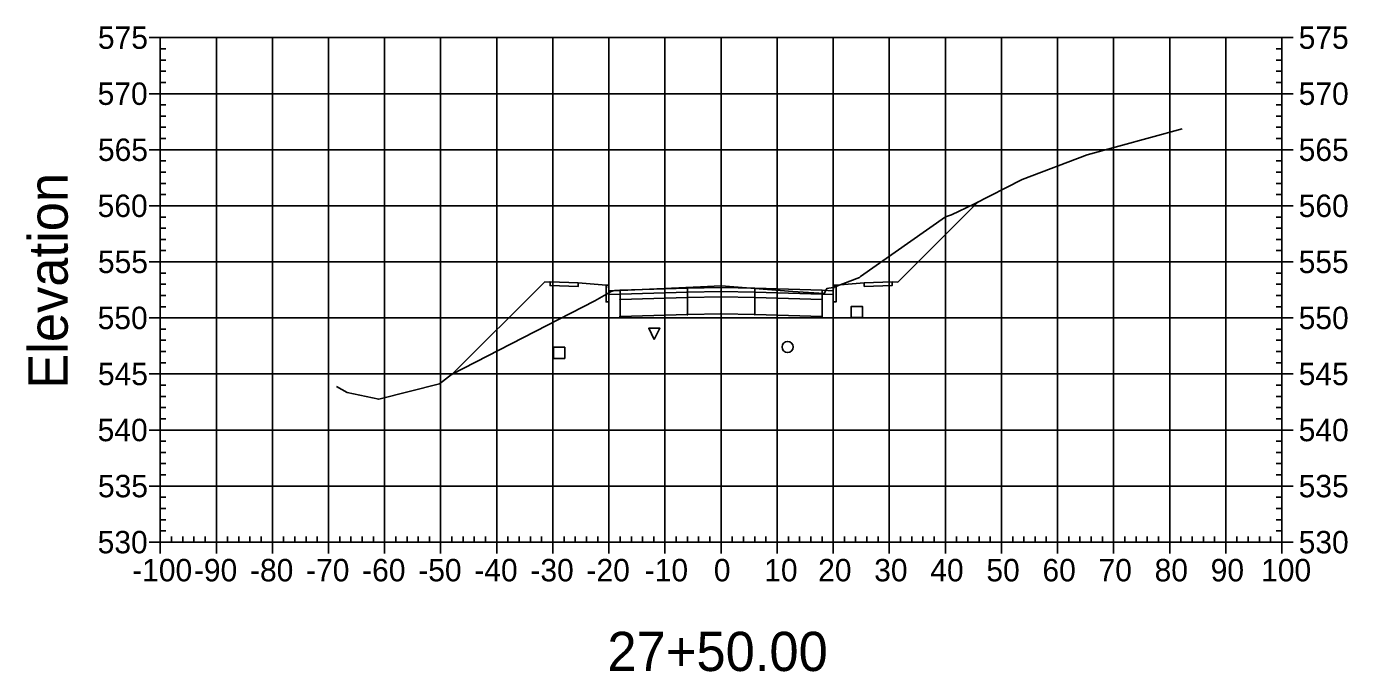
# Model space of a CAD drawing. Extents: x 704834 to 709892, y 372981 to 377533.
# Drawn here: x 708281 to 708516.6, y 376297.7 to 376412.8 of the extents above; entities that cross this region are included whole.
import ezdxf

# ---------------------------------------------------------------- set-up
doc = ezdxf.new("R2010")
doc.units = 0
for name, color, linetype in [('1', 7, 'Continuous'), ('10', 7, 'Continuous'), ('13', 7, 'Continuous'), ('14', 7, 'Continuous'), ('4', 7, 'Continuous'), ('57', 7, 'Continuous'), ('60', 7, 'Continuous'), ('Default_Xsect', 7, 'Continuous'), ('Existing', 7, 'Continuous')]:
    doc.layers.add(name, color=color, linetype=linetype)

msp = doc.modelspace()

# ---------------------------------------------------------------- linework, layer by layer
for points in [[(708436.41, 376367.22), (708450.62, 376381.43)], [(708373.41, 376367.22), (708356.96, 376350.77)], [(708374.41, 376367.26), (708373.41, 376367.22)], [(708384.41, 376366.66), (708379.41, 376367.06)], [(708425.41, 376366.66), (708430.41, 376367.06)], [(708435.41, 376367.26), (708436.41, 376367.22)]]:
    msp.add_lwpolyline(points)
for points in [[(708379.41, 376367.06), (708374.41, 376367.26), (708374.41, 376366.6), (708379.41, 376366.4)], [(708384.91, 376365.66), (708384.83, 376366.66), (708384.41, 376366.66), (708384.41, 376363.66), (708384.91, 376363.66)], [(708404.91, 376366.22), (708398.91, 376366.1), (708398.91, 376365.44), (708404.91, 376365.56)], [(708404.91, 376365.56), (708410.91, 376365.44), (708410.91, 376366.1), (708404.91, 376366.22)], [(708424.91, 376363.66), (708425.41, 376363.66), (708425.41, 376366.66), (708425, 376366.66), (708424.91, 376365.66)], [(708430.41, 376366.4), (708435.41, 376366.6), (708435.41, 376367.26), (708430.41, 376367.06)], [(708386.91, 376365.74), (708384.91, 376365.66), (708384.91, 376365), (708386.91, 376365.08)], [(708386.86, 376364.03), (708386.96, 376364.03), (708386.96, 376364.13), (708386.86, 376364.13)], [(708398.91, 376366.1), (708386.91, 376365.74), (708386.91, 376365.08), (708398.91, 376365.44)], [(708398.91, 376365.44), (708386.91, 376365.08), (708386.91, 376364.08), (708398.91, 376364.44)], [(708398.91, 376364.44), (708386.91, 376364.08), (708386.91, 376361.08), (708398.91, 376361.44)], [(708398.86, 376365.39), (708398.96, 376365.39), (708398.96, 376365.49), (708398.86, 376365.49)], [(708398.86, 376364.39), (708398.96, 376364.39), (708398.96, 376364.49), (708398.86, 376364.49)], [(708404.91, 376365.56), (708398.91, 376365.44), (708398.91, 376364.44), (708404.91, 376364.56)], [(708404.91, 376364.56), (708398.91, 376364.44), (708398.91, 376361.44), (708404.91, 376361.56)], [(708404.86, 376365.51), (708404.96, 376365.51), (708404.96, 376365.61), (708404.86, 376365.61)], [(708404.86, 376364.51), (708404.96, 376364.51), (708404.96, 376364.61), (708404.86, 376364.61)], [(708404.91, 376364.56), (708410.91, 376364.44), (708410.91, 376365.44), (708404.91, 376365.56)], [(708404.91, 376361.56), (708410.91, 376361.44), (708410.91, 376364.44), (708404.91, 376364.56)], [(708410.86, 376365.39), (708410.96, 376365.39), (708410.96, 376365.49), (708410.86, 376365.49)], [(708410.86, 376364.39), (708410.96, 376364.39), (708410.96, 376364.49), (708410.86, 376364.49)], [(708410.91, 376365.44), (708422.91, 376365.08), (708422.91, 376365.74), (708410.91, 376366.1)], [(708410.91, 376364.44), (708422.91, 376364.08), (708422.91, 376365.08), (708410.91, 376365.44)], [(708410.91, 376361.44), (708422.91, 376361.08), (708422.91, 376364.08), (708410.91, 376364.44)], [(708422.86, 376364.03), (708422.96, 376364.03), (708422.96, 376364.13), (708422.86, 376364.13)], [(708422.91, 376365.08), (708424.91, 376365), (708424.91, 376365.66), (708422.91, 376365.74)], [(708398.86, 376361.39), (708398.96, 376361.39), (708398.96, 376361.49), (708398.86, 376361.49)], [(708404.86, 376361.51), (708404.96, 376361.51), (708404.96, 376361.61), (708404.86, 376361.61)], [(708410.86, 376361.39), (708410.96, 376361.39), (708410.96, 376361.49), (708410.86, 376361.49)], [(708386.86, 376361.03), (708386.96, 376361.03), (708386.96, 376361.13), (708386.86, 376361.13)], [(708422.86, 376361.03), (708422.96, 376361.03), (708422.96, 376361.13), (708422.86, 376361.13)]]:
    msp.add_lwpolyline(points, close=True)
at = {"layer": '1'}
msp.add_lwpolyline([(708393.01, 376356.98), (708392.01, 376358.98), (708394.01, 376358.98)], close=True, dxfattribs=at)
at = {"layer": '10'}
msp.add_lwpolyline([(708375.05, 376353.58), (708377.05, 376353.58), (708377.05, 376355.58), (708375.05, 376355.58)], close=True, dxfattribs=at)
at = {"layer": '13'}
msp.add_circle((708416.78, 376355.63), 1, dxfattribs=at)
at = {"layer": '14'}
for points in [[(708450.62, 376381.43), (708450.62, 376381.48), (708450.62, 376381.43), (708450.57, 376381.43), (708450.62, 376381.43), (708450.62, 376381.38), (708450.62, 376381.43), (708450.67, 376381.43)], [(708404.91, 376366.22), (708404.91, 376366.27), (708404.91, 376366.22), (708404.86, 376366.22), (708404.91, 376366.22), (708404.91, 376366.17), (708404.91, 376366.22), (708404.96, 376366.22)], [(708386.91, 376365.74), (708386.91, 376365.79), (708386.91, 376365.74), (708386.86, 376365.74), (708386.91, 376365.74), (708386.91, 376365.69), (708386.91, 376365.74), (708386.96, 376365.74)], [(708422.91, 376365.74), (708422.91, 376365.79), (708422.91, 376365.74), (708422.86, 376365.74), (708422.91, 376365.74), (708422.91, 376365.69), (708422.91, 376365.74), (708422.96, 376365.74)], [(708356.96, 376350.77), (708356.96, 376350.82), (708356.96, 376350.77), (708356.91, 376350.77), (708356.96, 376350.77), (708356.96, 376350.72), (708356.96, 376350.77), (708357.01, 376350.77)]]:
    msp.add_lwpolyline(points, dxfattribs=at)
at = {"layer": '4'}
msp.add_lwpolyline([(708428.13, 376360.87), (708430.13, 376360.87), (708430.13, 376362.87), (708428.13, 376362.87)], close=True, dxfattribs=at)
at = {"layer": '57'}
for p, q in [((708302.91, 376410.82), (708304.91, 376410.82)), ((708304.91, 376410.82), (708504.91, 376410.82)), ((708304.91, 376320.82), (708304.91, 376410.82)), ((708304.91, 376320.82), (708304.91, 376410.82)), ((708304.91, 376408.82), (708305.91, 376408.82)), ((708314.91, 376320.82), (708314.91, 376410.82)), ((708324.91, 376320.82), (708324.91, 376410.82)), ((708334.91, 376320.82), (708334.91, 376410.82)), ((708344.91, 376320.82), (708344.91, 376410.82)), ((708354.91, 376320.82), (708354.91, 376410.82)), ((708364.91, 376320.82), (708364.91, 376410.82)), ((708374.91, 376320.82), (708374.91, 376410.82)), ((708384.91, 376320.82), (708384.91, 376410.82)), ((708394.91, 376320.82), (708394.91, 376410.82)), ((708404.91, 376320.82), (708404.91, 376410.82)), ((708414.91, 376320.82), (708414.91, 376410.82)), ((708424.91, 376320.82), (708424.91, 376410.82)), ((708434.91, 376320.82), (708434.91, 376410.82)), ((708444.91, 376320.82), (708444.91, 376410.82)), ((708454.91, 376320.82), (708454.91, 376410.82)), ((708464.91, 376320.82), (708464.91, 376410.82)), ((708474.91, 376320.82), (708474.91, 376410.82)), ((708484.91, 376320.82), (708484.91, 376410.82)), ((708494.91, 376320.82), (708494.91, 376410.82)), ((708504.91, 376408.82), (708503.91, 376408.82)), ((708504.91, 376320.82), (708504.91, 376410.82)), ((708504.91, 376320.82), (708504.91, 376410.82)), ((708506.91, 376410.82), (708504.91, 376410.82)), ((708304.91, 376406.82), (708305.91, 376406.82)), ((708504.91, 376406.82), (708503.91, 376406.82)), ((708304.91, 376404.82), (708305.91, 376404.82)), ((708504.91, 376404.82), (708503.91, 376404.82)), ((708304.91, 376402.82), (708305.91, 376402.82)), ((708504.91, 376402.82), (708503.91, 376402.82)), ((708302.91, 376400.82), (708304.91, 376400.82)), ((708304.91, 376400.82), (708504.91, 376400.82)), ((708506.91, 376400.82), (708504.91, 376400.82)), ((708304.91, 376398.82), (708305.91, 376398.82)), ((708304.91, 376396.82), (708305.91, 376396.82)), ((708504.91, 376398.82), (708503.91, 376398.82)), ((708504.91, 376396.82), (708503.91, 376396.82)), ((708304.91, 376394.82), (708305.91, 376394.82)), ((708504.91, 376394.82), (708503.91, 376394.82)), ((708304.91, 376392.82), (708305.91, 376392.82)), ((708504.91, 376392.82), (708503.91, 376392.82)), ((708302.91, 376390.82), (708304.91, 376390.82)), ((708304.91, 376390.82), (708504.91, 376390.82)), ((708506.91, 376390.82), (708504.91, 376390.82)), ((708304.91, 376388.82), (708305.91, 376388.82)), ((708504.91, 376388.82), (708503.91, 376388.82)), ((708304.91, 376386.82), (708305.91, 376386.82)), ((708504.91, 376386.82), (708503.91, 376386.82)), ((708304.91, 376384.82), (708305.91, 376384.82)), ((708304.91, 376382.82), (708305.91, 376382.82)), ((708504.91, 376384.82), (708503.91, 376384.82)), ((708504.91, 376382.82), (708503.91, 376382.82)), ((708302.91, 376380.82), (708304.91, 376380.82)), ((708304.91, 376380.82), (708504.91, 376380.82)), ((708506.91, 376380.82), (708504.91, 376380.82)), ((708304.91, 376378.82), (708305.91, 376378.82)), ((708504.91, 376378.82), (708503.91, 376378.82)), ((708304.91, 376376.82), (708305.91, 376376.82)), ((708504.91, 376376.82), (708503.91, 376376.82)), ((708304.91, 376374.82), (708305.91, 376374.82)), ((708504.91, 376374.82), (708503.91, 376374.82)), ((708304.91, 376372.82), (708305.91, 376372.82)), ((708504.91, 376372.82), (708503.91, 376372.82)), ((708302.91, 376370.82), (708304.91, 376370.82)), ((708304.91, 376370.82), (708504.91, 376370.82)), ((708304.91, 376368.82), (708305.91, 376368.82)), ((708504.91, 376368.82), (708503.91, 376368.82)), ((708506.91, 376370.82), (708504.91, 376370.82)), ((708304.91, 376366.82), (708305.91, 376366.82)), ((708504.91, 376366.82), (708503.91, 376366.82)), ((708304.91, 376364.82), (708305.91, 376364.82)), ((708504.91, 376364.82), (708503.91, 376364.82)), ((708304.91, 376362.82), (708305.91, 376362.82)), ((708504.91, 376362.82), (708503.91, 376362.82)), ((708302.91, 376360.82), (708304.91, 376360.82)), ((708304.91, 376360.82), (708504.91, 376360.82)), ((708506.91, 376360.82), (708504.91, 376360.82)), ((708304.91, 376358.82), (708305.91, 376358.82)), ((708304.91, 376356.82), (708305.91, 376356.82)), ((708504.91, 376358.82), (708503.91, 376358.82)), ((708504.91, 376356.82), (708503.91, 376356.82)), ((708304.91, 376354.82), (708305.91, 376354.82)), ((708504.91, 376354.82), (708503.91, 376354.82)), ((708304.91, 376352.82), (708305.91, 376352.82)), ((708504.91, 376352.82), (708503.91, 376352.82)), ((708302.91, 376350.82), (708304.91, 376350.82)), ((708304.91, 376350.82), (708504.91, 376350.82)), ((708506.91, 376350.82), (708504.91, 376350.82)), ((708304.91, 376348.82), (708305.91, 376348.82)), ((708504.91, 376348.82), (708503.91, 376348.82)), ((708304.91, 376346.82), (708305.91, 376346.82)), ((708504.91, 376346.82), (708503.91, 376346.82)), ((708304.91, 376344.82), (708305.91, 376344.82)), ((708304.91, 376342.82), (708305.91, 376342.82)), ((708504.91, 376344.82), (708503.91, 376344.82)), ((708504.91, 376342.82), (708503.91, 376342.82)), ((708302.91, 376340.82), (708304.91, 376340.82)), ((708304.91, 376340.82), (708504.91, 376340.82)), ((708506.91, 376340.82), (708504.91, 376340.82)), ((708304.91, 376338.82), (708305.91, 376338.82)), ((708504.91, 376338.82), (708503.91, 376338.82)), ((708304.91, 376336.82), (708305.91, 376336.82)), ((708504.91, 376336.82), (708503.91, 376336.82)), ((708304.91, 376334.82), (708305.91, 376334.82)), ((708504.91, 376334.82), (708503.91, 376334.82)), ((708302.91, 376330.82), (708304.91, 376330.82)), ((708304.91, 376332.82), (708305.91, 376332.82)), ((708304.91, 376330.82), (708504.91, 376330.82)), ((708504.91, 376332.82), (708503.91, 376332.82)), ((708506.91, 376330.82), (708504.91, 376330.82)), ((708304.91, 376328.82), (708305.91, 376328.82)), ((708504.91, 376328.82), (708503.91, 376328.82)), ((708304.91, 376326.82), (708305.91, 376326.82)), ((708504.91, 376326.82), (708503.91, 376326.82)), ((708304.91, 376324.82), (708305.91, 376324.82)), ((708504.91, 376324.82), (708503.91, 376324.82)), ((708304.91, 376322.82), (708305.91, 376322.82)), ((708306.91, 376320.82), (708306.91, 376321.82)), ((708308.91, 376320.82), (708308.91, 376321.82)), ((708310.91, 376320.82), (708310.91, 376321.82)), ((708312.91, 376320.82), (708312.91, 376321.82)), ((708316.91, 376320.82), (708316.91, 376321.82)), ((708318.91, 376320.82), (708318.91, 376321.82)), ((708320.91, 376320.82), (708320.91, 376321.82)), ((708322.91, 376320.82), (708322.91, 376321.82)), ((708326.91, 376320.82), (708326.91, 376321.82)), ((708328.91, 376320.82), (708328.91, 376321.82)), ((708330.91, 376320.82), (708330.91, 376321.82)), ((708332.91, 376320.82), (708332.91, 376321.82)), ((708336.91, 376320.82), (708336.91, 376321.82)), ((708338.91, 376320.82), (708338.91, 376321.82)), ((708340.91, 376320.82), (708340.91, 376321.82)), ((708342.91, 376320.82), (708342.91, 376321.82)), ((708346.91, 376320.82), (708346.91, 376321.82)), ((708348.91, 376320.82), (708348.91, 376321.82)), ((708350.91, 376320.82), (708350.91, 376321.82)), ((708352.91, 376320.82), (708352.91, 376321.82)), ((708356.91, 376320.82), (708356.91, 376321.82)), ((708358.91, 376320.82), (708358.91, 376321.82)), ((708360.91, 376320.82), (708360.91, 376321.82)), ((708362.91, 376320.82), (708362.91, 376321.82)), ((708366.91, 376320.82), (708366.91, 376321.82)), ((708368.91, 376320.82), (708368.91, 376321.82)), ((708370.91, 376320.82), (708370.91, 376321.82)), ((708372.91, 376320.82), (708372.91, 376321.82)), ((708376.91, 376320.82), (708376.91, 376321.82)), ((708378.91, 376320.82), (708378.91, 376321.82)), ((708380.91, 376320.82), (708380.91, 376321.82)), ((708382.91, 376320.82), (708382.91, 376321.82)), ((708386.91, 376320.82), (708386.91, 376321.82)), ((708388.91, 376320.82), (708388.91, 376321.82)), ((708390.91, 376320.82), (708390.91, 376321.82)), ((708392.91, 376320.82), (708392.91, 376321.82)), ((708396.91, 376320.82), (708396.91, 376321.82)), ((708398.91, 376320.82), (708398.91, 376321.82)), ((708400.91, 376320.82), (708400.91, 376321.82)), ((708402.91, 376320.82), (708402.91, 376321.82)), ((708406.91, 376320.82), (708406.91, 376321.82)), ((708408.91, 376320.82), (708408.91, 376321.82)), ((708410.91, 376320.82), (708410.91, 376321.82)), ((708412.91, 376320.82), (708412.91, 376321.82)), ((708416.91, 376320.82), (708416.91, 376321.82)), ((708418.91, 376320.82), (708418.91, 376321.82)), ((708420.91, 376320.82), (708420.91, 376321.82)), ((708422.91, 376320.82), (708422.91, 376321.82)), ((708426.91, 376320.82), (708426.91, 376321.82)), ((708428.91, 376320.82), (708428.91, 376321.82)), ((708430.91, 376320.82), (708430.91, 376321.82)), ((708432.91, 376320.82), (708432.91, 376321.82)), ((708436.91, 376320.82), (708436.91, 376321.82)), ((708438.91, 376320.82), (708438.91, 376321.82)), ((708440.91, 376320.82), (708440.91, 376321.82)), ((708442.91, 376320.82), (708442.91, 376321.82)), ((708446.91, 376320.82), (708446.91, 376321.82)), ((708448.91, 376320.82), (708448.91, 376321.82)), ((708450.91, 376320.82), (708450.91, 376321.82)), ((708452.91, 376320.82), (708452.91, 376321.82)), ((708456.91, 376320.82), (708456.91, 376321.82)), ((708458.91, 376320.82), (708458.91, 376321.82)), ((708460.91, 376320.82), (708460.91, 376321.82)), ((708462.91, 376320.82), (708462.91, 376321.82)), ((708466.91, 376320.82), (708466.91, 376321.82)), ((708468.91, 376320.82), (708468.91, 376321.82)), ((708470.91, 376320.82), (708470.91, 376321.82)), ((708472.91, 376320.82), (708472.91, 376321.82)), ((708476.91, 376320.82), (708476.91, 376321.82)), ((708478.91, 376320.82), (708478.91, 376321.82)), ((708480.91, 376320.82), (708480.91, 376321.82)), ((708482.91, 376320.82), (708482.91, 376321.82)), ((708486.91, 376320.82), (708486.91, 376321.82)), ((708488.91, 376320.82), (708488.91, 376321.82)), ((708490.91, 376320.82), (708490.91, 376321.82)), ((708492.91, 376320.82), (708492.91, 376321.82)), ((708496.91, 376320.82), (708496.91, 376321.82)), ((708498.91, 376320.82), (708498.91, 376321.82)), ((708500.91, 376320.82), (708500.91, 376321.82)), ((708502.91, 376320.82), (708502.91, 376321.82)), ((708504.91, 376322.82), (708503.91, 376322.82)), ((708302.91, 376320.82), (708304.91, 376320.82)), ((708304.91, 376320.82), (708504.91, 376320.82)), ((708304.91, 376320.82), (708504.91, 376320.82)), ((708304.91, 376318.82), (708304.91, 376320.82)), ((708314.91, 376318.82), (708314.91, 376320.82)), ((708324.91, 376318.82), (708324.91, 376320.82)), ((708334.91, 376318.82), (708334.91, 376320.82)), ((708344.91, 376318.82), (708344.91, 376320.82)), ((708354.91, 376318.82), (708354.91, 376320.82)), ((708364.91, 376318.82), (708364.91, 376320.82)), ((708374.91, 376318.82), (708374.91, 376320.82)), ((708384.91, 376318.82), (708384.91, 376320.82)), ((708394.91, 376318.82), (708394.91, 376320.82)), ((708404.91, 376318.82), (708404.91, 376320.82)), ((708414.91, 376318.82), (708414.91, 376320.82)), ((708424.91, 376318.82), (708424.91, 376320.82)), ((708434.91, 376318.82), (708434.91, 376320.82)), ((708444.91, 376318.82), (708444.91, 376320.82)), ((708454.91, 376318.82), (708454.91, 376320.82)), ((708464.91, 376318.82), (708464.91, 376320.82)), ((708474.91, 376318.82), (708474.91, 376320.82)), ((708484.91, 376318.82), (708484.91, 376320.82)), ((708494.91, 376318.82), (708494.91, 376320.82)), ((708504.91, 376318.82), (708504.91, 376320.82)), ((708506.91, 376320.82), (708504.91, 376320.82))]:
    msp.add_line(p, q, dxfattribs=at)
at = {"layer": 'Default_Xsect'}
msp.add_lwpolyline([(708356.96, 376350.77), (708373.41, 376367.22), (708374.41, 376367.26), (708379.41, 376367.06), (708384.41, 376366.66), (708384.83, 376366.66), (708384.91, 376365.66), (708386.91, 376365.74), (708398.91, 376366.1), (708404.91, 376366.22), (708410.91, 376366.1), (708422.91, 376365.74), (708424.91, 376365.66), (708425, 376366.66), (708425.41, 376366.66), (708430.41, 376367.06), (708435.41, 376367.26), (708436.41, 376367.22), (708450.62, 376381.43)], dxfattribs=at)
at = {"layer": 'Existing'}
msp.add_lwpolyline([(708336.31, 376348.57), (708338.22, 376347.49), (708343.87, 376346.32), (708354.69, 376349.08), (708356.86, 376350.72), (708382.43, 376363.86), (708385.31, 376365.55), (708385.67, 376365.64), (708401.26, 376366.36), (708404.92, 376366.53), (708417.7, 376365.56), (708423.31, 376365.18), (708423.71, 376365.94), (708423.8, 376366.09), (708424.91, 376366.27), (708429.6, 376368.04), (708429.61, 376368.05), (708429.8, 376368.18), (708444.96, 376378.83), (708445.99, 376379.2), (708449.99, 376381.1), (708458.6, 376385.52), (708470.18, 376389.94), (708487.12, 376394.58)], dxfattribs=at)

# ---------------------------------------------------------------- texts
at = {"layer": '1'}
msp.add_text('27+50.00', height=7, dxfattribs=at).set_placement((708384.64, 376297.82))
at = {"layer": '14'}
for p in [(708374.38, 376367.21), (708374.38, 376366.55), (708379.38, 376366.35), (708430.38, 376366.35), (708435.38, 376367.21), (708435.38, 376366.55)]:
    msp.add_text('+', height=0.1, dxfattribs=at).set_placement(p)
at = {"layer": '57'}
for s, p in [('575', (708293.79, 376408.82)), ('575', (708507.91, 376408.82)), ('570', (708293.74, 376398.82)), ('570', (708507.91, 376398.82)), ('565', (708293.79, 376388.82)), ('565', (708507.91, 376388.82)), ('560', (708293.74, 376378.82)), ('560', (708507.91, 376378.82)), ('555', (708293.79, 376368.82)), ('555', (708507.91, 376368.82)), ('550', (708293.74, 376358.82)), ('550', (708507.91, 376358.82)), ('545', (708293.79, 376348.82)), ('545', (708507.91, 376348.82)), ('540', (708293.74, 376338.82)), ('540', (708507.91, 376338.82)), ('535', (708293.79, 376328.82)), ('535', (708507.91, 376328.82)), ('530', (708293.74, 376318.82)), ('530', (708507.91, 376318.82)), ('-100', (708299.9, 376313.82)), ('-90', (708310.91, 376313.82)), ('-80', (708320.91, 376313.82)), ('-70', (708330.91, 376313.82)), ('-60', (708340.91, 376313.82)), ('-50', (708350.91, 376313.82)), ('-40', (708360.91, 376313.82)), ('-30', (708370.91, 376313.82)), ('-20', (708380.91, 376313.82)), ('-10', (708391.3, 376313.82)), ('0', (708403.62, 376313.82)), ('10', (708412.61, 376313.82)), ('20', (708422.22, 376313.82)), ('30', (708432.22, 376313.82)), ('40', (708442.22, 376313.82)), ('50', (708452.22, 376313.82)), ('60', (708462.22, 376313.82)), ('70', (708472.22, 376313.82)), ('80', (708482.22, 376313.82)), ('90', (708492.22, 376313.82)), ('100', (708501.21, 376313.82))]:
    msp.add_text(s, height=4, dxfattribs=at).set_placement(p)
at = {"layer": '60'}
msp.add_text('Elevation', height=7, rotation=90, dxfattribs=at).set_placement((708288.41, 376348.18))

doc.saveas('drawing.dxf')
